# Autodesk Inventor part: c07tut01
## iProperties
Created: 2002-01
Part Number: c07tut01
Document SubType Name: Modeling
Designer: ***
Control State: 0
Master: False
Checked Out: False
Shininess: 77.0
Length Units: 11269
Angle Units: 11279
Time Units: 11290
Mass Units: 11283
Length Display Precision: 3
Angle Display Precision: 2
Density: 0.0
Volumn: 0.0
Area: 0.0
PropertySet Name: Model Information
Author: ***
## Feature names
1. Sweep1
2. Shell1
3. Extrusion1
4. Extrusion2
5. Hole1
6. Fillet1
7. Extrusion3
8. Extrusion4
9. Hole2
10. Hole3
11. Circular Pattern1
12. Circular Pattern2
13. Hole4
